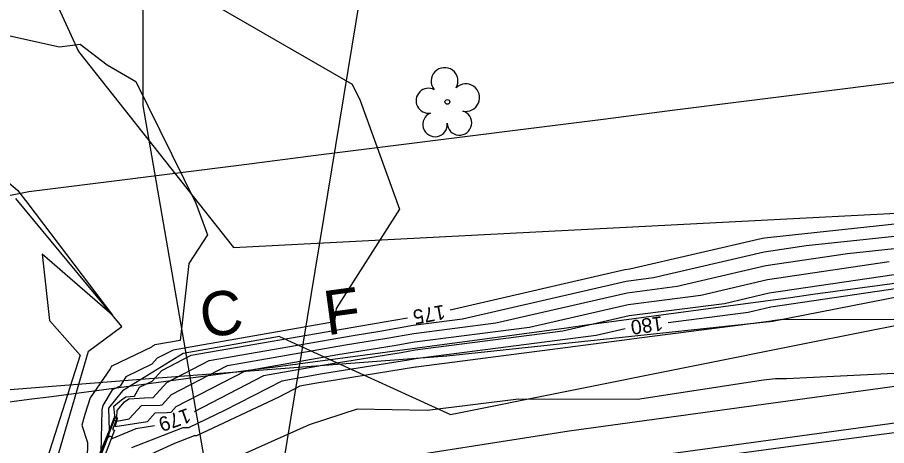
# Model space of a CAD drawing. Extents: x 2086416 to 2115205, y 575507 to 632762.
# Drawn here: x 2111557.3 to 2111677.4, y 581680.1 to 581739.2 of the extents above; entities that cross this region are included whole.
import ezdxf

# ---------------------------------------------------------------- set-up
doc = ezdxf.new("R2010")
doc.units = 0
for name, color, linetype in [('DTM Contours Major', 7, 'Continuous'), ('DTM Contours Major Text', 7, 'Continuous'), ('DTM Contours Minor', 7, 'Continuous'), ('DTM Contours Minor Text', 7, 'Continuous'), ('Exist Hydro Stream or Body of Water', 7, 'Continuous'), ('Exist Hydrographic FEMA Cross Section', 7, 'Continuous'), ('Exist Hydrographic Stream Bed', 7, 'Continuous'), ('Exist Right of Way Line', 7, 'Continuous'), ('Exist Roads EOP', 7, 'Continuous'), ('Exist Structure Major Bridge WW', 7, 'Continuous'), ('Exist Vegetation Tree CELL', 7, 'Continuous'), ('Exist Vegetation Woods Line', 7, 'Continuous'), ('Prop EOT', 7, 'Continuous'), ('Prop Horizontal Alignment Station Label', 7, 'Continuous'), ('Prop Paved Shoulder', 7, 'Continuous'), ('Prop SS Cut Line', 7, 'Continuous'), ('Prop SS Cut Text', 7, 'Continuous'), ('Prop SS Fill Line', 7, 'Continuous'), ('Prop SS Fill Text', 7, 'Continuous')]:
    doc.layers.add(name, color=color, linetype=linetype)

# ---------------------------------------------------------------- blocks, each defined once
blk = doc.blocks.new('EXIST VEGETATION TREE')
at = {"layer": 'Exist Vegetation Tree CELL'}
blk.add_line((0, 0), (0, 0), dxfattribs=at)
blk.add_circle((0, 0), 0.00652, dxfattribs=at)
for centre, radius, start, end in [((-0.0077, 0.0575), 0.0371, 330.1651, 219.7134), ((0.051, 0.0118), 0.038, 257.1011, 134.1999), ((-0.0521, 0.0031), 0.0345, 62.6636, 279.3457), ((-0.0341, -0.0624), 0.0338, 111.5671, 6.231), ((0.0335, -0.058), 0.034, 181.2822, 74.56)]:
    blk.add_arc(centre, radius, start, end, dxfattribs=at)

msp = doc.modelspace()

# ---------------------------------------------------------------- linework, layer by layer
at = {"layer": 'DTM Contours Major'}
for points in [[(2111617.1, 581698.85), (2111641.26, 581704.4), (2111641.96, 581704.49), (2111660.29, 581708.76), (2111660.56, 581708.8), (2111690.12, 581711.96), (2111707.48, 581713.81), (2111708.18, 581713.93), (2111715.64, 581714.84)], [(2111746.21, 581711.02), (2111744.42, 581710.79), (2111740.33, 581710.21), (2111740.15, 581710.16), (2111739.89, 581710.15), (2111710.46, 581706), (2111704.42, 581705.57), (2111692.08, 581703.63), (2111691.03, 581703.52), (2111689.24, 581703.33), (2111661.42, 581699.22), (2111658.28, 581698.49), (2111647.23, 581697.07)], [(2111568.39, 581677.72), (2111570.78, 581684.17), (2111570.79, 581684.17), (2111570.79, 581684.25), (2111570.65, 581685.53), (2111571.69, 581686.42), (2111572.31, 581686.85), (2111573.5, 581686.94), (2111574.21, 581688.15), (2111575.95, 581688.97), (2111577.3, 581690.48), (2111581.33, 581692.57), (2111604.78, 581696.65), (2111606.4, 581696.91), (2111611.21, 581697.76)], [(2111641.29, 581696.23), (2111637.3, 581695.31), (2111612.35, 581692.09), (2111611.36, 581691.91), (2111599.5, 581689.99), (2111593.85, 581689.01), (2111585.96, 581684.92), (2111580.95, 581682.57), (2111580.17, 581682.56), (2111573.08, 581679.8)]]:
    msp.add_lwpolyline(points, dxfattribs=at)
at = {"layer": 'DTM Contours Minor'}
for points in [[(2111582.17, 581742.39), (2111603.57, 581729.99), (2111604.67, 581727.75), (2111610.14, 581712.75), (2111601.35, 581699.02), (2111601.14, 581697.17), (2111578.83, 581693.28), (2111576.64, 581692.15), (2111575.91, 581691.33), (2111572.29, 581689.61), (2111571.53, 581688.32), (2111570.42, 581687.8), (2111569.11, 581685.65), (2111569.01, 581685.02), (2111568.86, 581679.13)], [(2111555.04, 581736.97), (2111563.15, 581735.16), (2111565.98, 581735.53), (2111569.71, 581732.7), (2111573.71, 581730.38), (2111581.99, 581713.56), (2111583.57, 581709.22), (2111581.03, 581705.26), (2111579.81, 581694.6), (2111576.33, 581693.99), (2111575.99, 581693.82), (2111575.87, 581693.69), (2111570.36, 581691.07), (2111570.35, 581691.05), (2111570.34, 581691.05), (2111570.14, 581690.71), (2111567.36, 581686.68), (2111566.66, 581684.37), (2111566.24, 581682.91), (2111567.02, 581680.5), (2111566.85, 581673.86)], [(2111554.56, 581717.65), (2111557.36, 581715.39), (2111558.77, 581713.51), (2111570.46, 581698.12), (2111560.75, 581706.53), (2111561.78, 581697.35), (2111565.99, 581692.59), (2111561.42, 581678.3), (2111560.17, 581674.93), (2111560.63, 581673.94), (2111560, 581669.27), (2111560.03, 581668.96), (2111560.71, 581660.16), (2111561.06, 581659.54), (2111561.4, 581658.89), (2111569.8, 581645.9), (2111570.55, 581641.09), (2111570.69, 581640.85), (2111570.83, 581641.04), (2111571.48, 581641.08), (2111571.48, 581641.08), (2111571.48, 581641.09), (2111571.57, 581640.98), (2111575.14, 581635.69)], [(2111778.53, 581716.52), (2111760.29, 581714.29), (2111743.84, 581712.22), (2111739.7, 581711.72), (2111714.98, 581708.61), (2111709.96, 581708), (2111695.16, 581705.67), (2111690.85, 581705.21), (2111683.5, 581704.42), (2111661.19, 581701.13), (2111655.01, 581699.69), (2111641.87, 581698), (2111632.68, 581695.88), (2111612.27, 581693.25), (2111610.37, 581692.91), (2111600.55, 581691.33), (2111591.35, 581689.72), (2111581.74, 581684.75)], [(2111569.26, 581679.92), (2111570.8, 581684.09), (2111571.06, 581684.04), (2111571.12, 581684.94), (2111572.14, 581686.13), (2111572.74, 581686.54), (2111574.87, 581686.7), (2111576.06, 581686.72), (2111576.08, 581686.72), (2111577.96, 581688.82), (2111583.84, 581691.86), (2111603.73, 581695.32), (2111607.39, 581695.91), (2111612.02, 581696.73), (2111618.81, 581697.6), (2111641.42, 581702.8), (2111645.22, 581703.29), (2111660.52, 581706.85), (2111666.29, 581707.71), (2111690.3, 581710.27)], [(2111566.54, 581672.9), (2111570.12, 581682.11), (2111570.82, 581684.01), (2111571.02, 581683.97), (2111571.12, 581683.93), (2111571.04, 581683.49), (2111572.78, 581683.78), (2111574.45, 581685.63), (2111577.05, 581685.69), (2111577.33, 581685.71), (2111578.62, 581687.15), (2111586.34, 581691.15), (2111602.67, 581693.99), (2111608.38, 581694.91), (2111612.1, 581695.57), (2111623.43, 581697.03), (2111641.57, 581701.2), (2111648.49, 581702.09), (2111660.74, 581704.95), (2111672.03, 581706.61), (2111690.48, 581708.58)], [(2111771.48, 581708.94), (2111760.55, 581707.39), (2111751.32, 581706.07), (2111741.05, 581703.18), (2111726.36, 581703.03), (2111711.26, 581700.9), (2111699.31, 581700.06), (2111691.64, 581698.04), (2111679.98, 581697.46), (2111663.05, 581697.52), (2111661.64, 581697.31), (2111661.54, 581697.28), (2111642.18, 581694.8), (2111641.92, 581694.74), (2111612.43, 581690.93), (2111612.35, 581690.91), (2111598.44, 581688.66), (2111596.35, 581688.3), (2111593.43, 581686.79), (2111582.07, 581681.44), (2111581.77, 581681.43), (2111579.05, 581680.38), (2111575.31, 581678.67)], [(2111566.55, 581672.89), (2111570.69, 581683.54), (2111570.77, 581683.6), (2111570.96, 581683.55), (2111571.01, 581683.53), (2111570.84, 581682.71), (2111575.32, 581683.44), (2111576.38, 581684.62), (2111578.04, 581684.65), (2111578.57, 581684.69), (2111579.28, 581685.48), (2111588.84, 581690.43), (2111601.61, 581692.66), (2111609.37, 581693.91), (2111612.19, 581694.41), (2111628.06, 581696.46), (2111641.72, 581699.6), (2111651.75, 581700.89), (2111660.97, 581703.04), (2111677.77, 581705.52)], [(2111775.95, 581702.18), (2111765.88, 581701.69), (2111760.91, 581700.98), (2111757.86, 581700.67), (2111741.95, 581696.21), (2111712.84, 581695.91), (2111712.06, 581695.8), (2111711.43, 581695.75), (2111692.47, 581690.75), (2111663.6, 581689.32), (2111662.08, 581689.32), (2111660.39, 581689.12), (2111642.99, 581686.48), (2111626.56, 581686.5), (2111613.94, 581684.95), (2111604.27, 581685.12), (2111597.65, 581682.97), (2111586.74, 581678.08), (2111579.19, 581676.52)], [(2111576.27, 581682.84), (2111573.71, 581682.42), (2111570.37, 581681.02), (2111570.38, 581681.33), (2111570.36, 581681.36), (2111570.32, 581681.3), (2111570.11, 581681.39), (2111569.76, 581681.12), (2111566.56, 581672.88), (2111566.54, 581672.9), (2111566.38, 581672.88), (2111566.24, 581672.86), (2111566.42, 581671.65), (2111567.12, 581666.77), (2111567.76, 581662.76), (2111570.69, 581642.93), (2111570.61, 581642.81), (2111570.86, 581641.18), (2111571.15, 581641.2), (2111571.31, 581641.22), (2111571.26, 581641.66)]]:
    msp.add_lwpolyline(points, dxfattribs=at)
at = {"layer": 'Exist Hydro Stream or Body of Water'}
msp.add_lwpolyline([(2111621.04, 581592.2), (2111611.64, 581604.33), (2111605.91, 581608.14), (2111600.48, 581607.01), (2111602.12, 581600.1), (2111601.11, 581599.2), (2111587.78, 581617.38), (2111576.69, 581633.34), (2111571.48, 581641.08), (2111570.64, 581641.03), (2111569.87, 581645.92), (2111561.21, 581659.64), (2111560.4, 581669.08), (2111561.77, 581674.66), (2111567.14, 581693.15), (2111571.77, 581696.53), (2111557.1, 581714.2)], dxfattribs=at)
at = {"layer": 'Exist Hydrographic FEMA Cross Section'}
msp.add_lwpolyline([(2111757.26, 581740.16), (2111747.34, 581738.91), (2111742.38, 581738.29), (2111737.42, 581737.66), (2111727.5, 581736.41), (2111717.58, 581735.16), (2111707.67, 581733.91), (2111697.75, 581732.65), (2111687.83, 581731.4), (2111677.92, 581730.15), (2111668, 581728.9), (2111658.08, 581727.65), (2111648.17, 581726.4), (2111638.25, 581725.14), (2111628.33, 581723.89), (2111618.42, 581722.64), (2111608.5, 581721.39), (2111598.58, 581720.14), (2111588.67, 581718.89), (2111578.75, 581717.64), (2111568.83, 581716.38), (2111558.92, 581715.13), (2111549.31, 581713.26)], dxfattribs=at)
at = {"layer": 'Exist Hydrographic Stream Bed'}
msp.add_lwpolyline([(2112129.65, 582477.71), (2111835.9, 582368.96), (2111727.15, 582231.15), (2111672.65, 582129.59), (2111610.9, 582009.96), (2111585.65, 581897.53), (2111574.65, 581806.9), (2111574.65, 581727.08), (2111582.9, 581679.52), (2111589.15, 581643.7), (2111621.9, 581589.33), (2111665.4, 581516.77), (2111701.65, 581379.01), (2111737.9, 581248.45), (2111785.15, 581103.39)], dxfattribs=at)
at = {"layer": 'Exist Right of Way Line'}
msp.add_arc((2108326.55, 606231.5), 24756.94, 277.393911, 277.856215, dxfattribs=at)
at = {"layer": 'Exist Roads EOP'}
msp.add_lwpolyline([(2111568.95, 581657.38), (2111567.48, 581667.28), (2111614.17, 581673.23), (2111663.5, 581679.94), (2111712.97, 581686.46), (2111762.01, 581693.34), (2111810.99, 581700.16), (2111860.08, 581706.99), (2111909.44, 581713.78), (2111958.29, 581720.29), (2112007.47, 581726.81), (2112052.56, 581733.02), (2112053.87, 581723.65)], dxfattribs=at)
msp.add_lwpolyline([(2111568.95, 581657.38), (2111567.48, 581667.28), (2111614.17, 581673.23), (2111663.5, 581679.94), (2111712.97, 581686.46), (2111762.01, 581693.34), (2111810.99, 581700.16), (2111860.08, 581706.99), (2111909.44, 581713.78), (2111958.29, 581720.29), (2112007.47, 581726.81), (2112052.56, 581733.02), (2112053.87, 581723.65)], dxfattribs=at)
at = {"layer": 'Exist Structure Major Bridge WW'}
msp.add_lwpolyline([(2111566.58, 581672.83), (2111566.85, 581673.52), (2111570.25, 581682.39), (2111570.84, 581683.94), (2111571.08, 581683.85), (2111570.48, 581682.3), (2111570.72, 581682.21), (2111567.32, 581673.34), (2111567.08, 581673.43), (2111566.66, 581672.32), (2111566.58, 581672.83)], dxfattribs=at)
at = {"layer": 'Exist Vegetation Woods Line'}
for points in [[(2111543, 581784.1), (2111565.77, 581734.52), (2111587.19, 581707.45), (2111708.99, 581713.78), (2111811.99, 581727.73), (2111909.41, 581740.4), (2112007.41, 581746.55), (2112041.96, 581749.79), (2112042.22, 581740.22)], [(2112042.22, 581740.22), (2112007.09, 581741.23), (2111957.14, 581737.86), (2111908.66, 581731.85), (2111808.65, 581718.24), (2111760.41, 581712.7), (2111710.34, 581706.77), (2111661.65, 581697.22), (2111616.66, 581692.44), (2111575, 581689.29), (2111546.91, 581687.08), (2111515.04, 581695.86), (2111502.17, 581702.85), (2111491.11, 581719.62), (2111479.28, 581746.11)]]:
    msp.add_lwpolyline(points, dxfattribs=at)
at = {"layer": 'Prop EOT'}
msp.add_line((2111430.06, 581649.33), (2112312.03, 581769.69), dxfattribs=at)
at = {"layer": 'Prop Horizontal Alignment Station Label'}
msp.add_line((2111591.21, 581660.22), (2111612.47, 581789.24), dxfattribs=at)
at = {"layer": 'Prop Paved Shoulder'}
for p, q in [((2111633.58, 581682.15), (2111994.42, 581731.39)), ((2111604.76, 581677.63), (2111633.58, 581682.15))]:
    msp.add_line(p, q, dxfattribs=at)
at = {"layer": 'Prop SS Cut Line'}
for p, q in [((2111593.56, 581695.16), (2111580.25, 581692.82)), ((2111580.25, 581692.82), (2111571.84, 581687.65)), ((2111571.84, 581687.65), (2111569.9, 581685.25)), ((2111569.9, 581685.25), (2111570.02, 581682.16)), ((2111570.02, 581682.16), (2111566.13, 581672.9))]:
    msp.add_line(p, q, dxfattribs=at)
at = {"layer": 'Prop SS Fill Line'}
for p, q in [((2111666.3, 581694.23), (2111715.42, 581704.07)), ((2111593.56, 581695.16), (2111617.18, 581684.41)), ((2111617.18, 581684.41), (2111666.3, 581694.23))]:
    msp.add_line(p, q, dxfattribs=at)

# ---------------------------------------------------------------- block references
at = {"layer": 'Exist Vegetation Tree CELL', "xscale": 50, "yscale": 50}
msp.add_blockref('EXIST VEGETATION TREE', (2111616.73, 581727.56), dxfattribs=at)

# ---------------------------------------------------------------- texts
at = {"layer": 'DTM Contours Major Text'}
for s, rotation, p in [('175', 190.4661, (2111616.23, 581699.57)), ('180', 188.0334, (2111646.37, 581697.99))]:
    msp.add_text(s, height=2, rotation=rotation, dxfattribs=at).set_placement(p)
at = {"layer": 'DTM Contours Minor Text'}
msp.add_text('179', height=2, rotation=199.2544, dxfattribs=at).set_placement((2111580.85, 581685.31))
at = {"layer": 'Prop SS Cut Text'}
msp.add_text('C', height=6.1, rotation=7.771, dxfattribs=at).set_placement((2111582.97, 581694.94))
at = {"layer": 'Prop SS Fill Text'}
msp.add_text('F', height=6.1, rotation=7.771, dxfattribs=at).set_placement((2111600.1, 581695.32))

doc.saveas('drawing.dxf')
